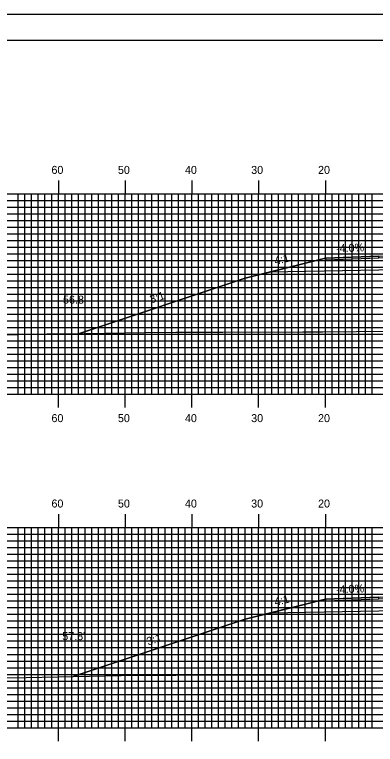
# Model space of a CAD drawing. Extents: x 1787763 to 1788106, y 442591 to 442811.
# Drawn here: x 1787862.1 to 1787916.1, y 442701.2 to 442810.5 of the extents above; entities that cross this region are included whole.
import ezdxf

# ---------------------------------------------------------------- set-up
doc = ezdxf.new("R2010")
doc.units = 0
for name, color, linetype in [('ANNOTATION', 7, 'Continuous'), ('BORDER', 7, 'Continuous'), ('D_Roadway_Centerline', 7, 'Continuous'), ('D_Roadway_Edge_Shoulder', 7, 'Continuous'), ('D_Roadway_SlopeLines', 7, 'Continuous'), ('D_Roadway_SubGrade', 7, 'Continuous'), ('D_Text_Standard', 7, 'Continuous'), ('H_V ANNOTATION', 7, 'Continuous'), ('MAJOR', 7, 'Continuous'), ('MINOR', 7, 'Continuous'), ('PLOT BOUNDARY', 7, 'Continuous'), ('S_Roadway_Centerline', 7, 'Continuous')]:
    doc.layers.add(name, color=color, linetype=linetype)

msp = doc.modelspace()

# ---------------------------------------------------------------- linework, layer by layer
at = {"layer": 'BORDER'}
msp.add_lwpolyline([(1787779.02, 442596.67), (1788099.02, 442596.67), (1788099.02, 442806.67), (1787779.02, 442806.67)], close=True, dxfattribs=at)
at = {"layer": 'D_Roadway_Centerline'}
for points in [[(1787871.78, 442762.76), (1787896.62, 442771.03), (1787900.25, 442771.94), (1787908.62, 442774.03), (1787916.62, 442774.35), (1787928.62, 442774.62), (1787940.62, 442774.88), (1787948.62, 442774.56), (1787956.98, 442772.47), (1787960.62, 442771.56), (1787984.39, 442763.64)], [(1787870.86, 442711.34), (1787896.62, 442719.93), (1787900.25, 442720.84), (1787908.62, 442722.93), (1787916.62, 442723.25), (1787928.62, 442723.51), (1787940.62, 442723.78), (1787948.62, 442723.46), (1787956.98, 442721.37), (1787960.62, 442720.46), (1787987.68, 442711.43)]]:
    msp.add_lwpolyline(points, dxfattribs=at)
at = {"layer": 'D_Roadway_Edge_Shoulder'}
for points in [[(1787916.62, 442774.35), (1787908.62, 442774.03), (1787908.62, 442773.78), (1787916.62, 442774.1)], [(1787916.62, 442723.25), (1787908.62, 442722.93), (1787908.62, 442722.68), (1787916.62, 442723)]]:
    msp.add_lwpolyline(points, close=True, dxfattribs=at)
at = {"layer": 'D_Roadway_SlopeLines'}
for points in [[(1787908.62, 442774.03), (1787896.62, 442771.03), (1787871.78, 442762.76)], [(1787908.62, 442722.93), (1787896.62, 442719.93), (1787870.86, 442711.34)]]:
    msp.add_lwpolyline(points, dxfattribs=at)
at = {"layer": 'D_Roadway_SubGrade'}
for points in [[(1787916.62, 442772.27), (1787900.25, 442771.94), (1787908.62, 442774.03), (1787908.62, 442773.78), (1787916.62, 442774.1), (1787928.62, 442774.37), (1787940.62, 442774.63), (1787948.62, 442774.31), (1787948.62, 442774.56), (1787956.98, 442772.47), (1787940.62, 442772.8), (1787928.62, 442772.54)], [(1787916.62, 442721.16), (1787900.25, 442720.84), (1787908.62, 442722.93), (1787908.62, 442722.68), (1787916.62, 442723), (1787928.62, 442723.26), (1787940.62, 442723.53), (1787948.62, 442723.21), (1787948.62, 442723.46), (1787956.98, 442721.37), (1787940.62, 442721.69), (1787928.62, 442721.43)]]:
    msp.add_lwpolyline(points, close=True, dxfattribs=at)
at = {"layer": 'MAJOR'}
for p, q in [((1787868.62, 442785.67), (1787868.62, 442783.67)), ((1787878.62, 442785.67), (1787878.62, 442783.67)), ((1787888.62, 442785.67), (1787888.62, 442783.67)), ((1787898.62, 442785.67), (1787898.62, 442783.67)), ((1787908.62, 442785.67), (1787908.62, 442783.67)), ((1787788.62, 442783.67), (1788068.62, 442783.67)), ((1787788.62, 442783.67), (1788068.62, 442783.67)), ((1787868.62, 442753.67), (1787868.62, 442783.67)), ((1787878.62, 442753.67), (1787878.62, 442783.67)), ((1787888.62, 442753.67), (1787888.62, 442783.67)), ((1787898.62, 442753.67), (1787898.62, 442783.67)), ((1787908.62, 442753.67), (1787908.62, 442783.67)), ((1787788.62, 442778.67), (1788068.62, 442778.67)), ((1787788.62, 442773.67), (1788068.62, 442773.67)), ((1787788.62, 442768.67), (1788068.62, 442768.67)), ((1787788.62, 442763.67), (1788068.62, 442763.67)), ((1787788.62, 442758.67), (1788068.62, 442758.67)), ((1787788.62, 442753.67), (1788068.62, 442753.67)), ((1787788.62, 442753.67), (1788068.62, 442753.67)), ((1787868.62, 442751.66), (1787868.62, 442753.67)), ((1787878.62, 442751.66), (1787878.62, 442753.67)), ((1787888.62, 442751.66), (1787888.62, 442753.67)), ((1787898.62, 442751.66), (1787898.62, 442753.67)), ((1787908.62, 442751.66), (1787908.62, 442753.67)), ((1787868.62, 442735.67), (1787868.62, 442733.67)), ((1787878.62, 442735.67), (1787878.62, 442733.67)), ((1787888.62, 442735.67), (1787888.62, 442733.67)), ((1787898.62, 442735.67), (1787898.62, 442733.67)), ((1787908.62, 442735.67), (1787908.62, 442733.67)), ((1787788.62, 442733.67), (1788068.62, 442733.67)), ((1787788.62, 442733.67), (1788068.62, 442733.67)), ((1787868.62, 442703.67), (1787868.62, 442733.67)), ((1787878.62, 442703.67), (1787878.62, 442733.67)), ((1787888.62, 442703.67), (1787888.62, 442733.67)), ((1787898.62, 442703.67), (1787898.62, 442733.67)), ((1787908.62, 442703.67), (1787908.62, 442733.67)), ((1787788.62, 442728.67), (1788068.62, 442728.67)), ((1787788.62, 442723.67), (1788068.62, 442723.67)), ((1787788.62, 442718.67), (1788068.62, 442718.67)), ((1787788.62, 442713.67), (1788068.62, 442713.67)), ((1787788.62, 442708.67), (1788068.62, 442708.67)), ((1787788.62, 442703.67), (1788068.62, 442703.67)), ((1787788.62, 442703.67), (1788068.62, 442703.67)), ((1787868.62, 442701.66), (1787868.62, 442703.67)), ((1787878.62, 442701.66), (1787878.62, 442703.67)), ((1787888.62, 442701.66), (1787888.62, 442703.67)), ((1787898.62, 442701.66), (1787898.62, 442703.67)), ((1787908.62, 442701.66), (1787908.62, 442703.67))]:
    msp.add_line(p, q, dxfattribs=at)
at = {"layer": 'MINOR'}
for p, q in [((1787862.62, 442753.67), (1787862.62, 442783.67)), ((1787863.62, 442753.67), (1787863.62, 442783.67)), ((1787864.62, 442753.67), (1787864.62, 442783.67)), ((1787865.62, 442753.67), (1787865.62, 442783.67)), ((1787866.62, 442753.67), (1787866.62, 442783.67)), ((1787867.62, 442753.67), (1787867.62, 442783.67)), ((1787869.62, 442753.67), (1787869.62, 442783.67)), ((1787870.62, 442753.67), (1787870.62, 442783.67)), ((1787871.62, 442753.67), (1787871.62, 442783.67)), ((1787872.62, 442753.67), (1787872.62, 442783.67)), ((1787873.62, 442753.67), (1787873.62, 442783.67)), ((1787874.62, 442753.67), (1787874.62, 442783.67)), ((1787875.62, 442753.67), (1787875.62, 442783.67)), ((1787876.62, 442753.67), (1787876.62, 442783.67)), ((1787877.62, 442753.67), (1787877.62, 442783.67)), ((1787879.62, 442753.67), (1787879.62, 442783.67)), ((1787880.62, 442753.67), (1787880.62, 442783.67)), ((1787881.62, 442753.67), (1787881.62, 442783.67)), ((1787882.62, 442753.67), (1787882.62, 442783.67)), ((1787883.62, 442753.67), (1787883.62, 442783.67)), ((1787884.62, 442753.67), (1787884.62, 442783.67)), ((1787885.62, 442753.67), (1787885.62, 442783.67)), ((1787886.62, 442753.67), (1787886.62, 442783.67)), ((1787887.62, 442753.67), (1787887.62, 442783.67)), ((1787889.62, 442753.67), (1787889.62, 442783.67)), ((1787890.62, 442753.67), (1787890.62, 442783.67)), ((1787891.62, 442753.67), (1787891.62, 442783.67)), ((1787892.62, 442753.67), (1787892.62, 442783.67)), ((1787893.62, 442753.67), (1787893.62, 442783.67)), ((1787894.62, 442753.67), (1787894.62, 442783.67)), ((1787895.62, 442753.67), (1787895.62, 442783.67)), ((1787896.62, 442753.67), (1787896.62, 442783.67)), ((1787897.62, 442753.67), (1787897.62, 442783.67)), ((1787899.62, 442753.67), (1787899.62, 442783.67)), ((1787900.62, 442753.67), (1787900.62, 442783.67)), ((1787901.62, 442753.67), (1787901.62, 442783.67)), ((1787902.62, 442753.67), (1787902.62, 442783.67)), ((1787903.62, 442753.67), (1787903.62, 442783.67)), ((1787904.62, 442753.67), (1787904.62, 442783.67)), ((1787905.62, 442753.67), (1787905.62, 442783.67)), ((1787906.62, 442753.67), (1787906.62, 442783.67)), ((1787907.62, 442753.67), (1787907.62, 442783.67)), ((1787909.62, 442753.67), (1787909.62, 442783.67)), ((1787910.62, 442753.67), (1787910.62, 442783.67)), ((1787911.62, 442753.67), (1787911.62, 442783.67)), ((1787912.62, 442753.67), (1787912.62, 442783.67)), ((1787913.62, 442753.67), (1787913.62, 442783.67)), ((1787914.62, 442753.67), (1787914.62, 442783.67)), ((1787915.62, 442753.67), (1787915.62, 442783.67)), ((1787788.62, 442782.67), (1788068.62, 442782.67)), ((1787788.62, 442781.67), (1788068.62, 442781.67)), ((1787788.62, 442780.67), (1788068.62, 442780.67)), ((1787788.62, 442779.67), (1788068.62, 442779.67)), ((1787788.62, 442777.67), (1788068.62, 442777.67)), ((1787788.62, 442776.67), (1788068.62, 442776.67)), ((1787788.62, 442775.67), (1788068.62, 442775.67)), ((1787788.62, 442774.67), (1788068.62, 442774.67)), ((1787788.62, 442772.67), (1788068.62, 442772.67)), ((1787788.62, 442771.67), (1788068.62, 442771.67)), ((1787788.62, 442770.67), (1788068.62, 442770.67)), ((1787788.62, 442769.67), (1788068.62, 442769.67)), ((1787788.62, 442767.67), (1788068.62, 442767.67)), ((1787788.62, 442766.67), (1788068.62, 442766.67)), ((1787788.62, 442765.67), (1788068.62, 442765.67)), ((1787788.62, 442764.67), (1788068.62, 442764.67)), ((1787788.62, 442762.67), (1788068.62, 442762.67)), ((1787788.62, 442761.67), (1788068.62, 442761.67)), ((1787788.62, 442760.67), (1788068.62, 442760.67)), ((1787788.62, 442759.67), (1788068.62, 442759.67)), ((1787788.62, 442757.67), (1788068.62, 442757.67)), ((1787788.62, 442756.67), (1788068.62, 442756.67)), ((1787788.62, 442755.67), (1788068.62, 442755.67)), ((1787788.62, 442754.67), (1788068.62, 442754.67)), ((1787862.62, 442703.67), (1787862.62, 442733.67)), ((1787863.62, 442703.67), (1787863.62, 442733.67)), ((1787864.62, 442703.67), (1787864.62, 442733.67)), ((1787865.62, 442703.67), (1787865.62, 442733.67)), ((1787866.62, 442703.67), (1787866.62, 442733.67)), ((1787867.62, 442703.67), (1787867.62, 442733.67)), ((1787869.62, 442703.67), (1787869.62, 442733.67)), ((1787870.62, 442703.67), (1787870.62, 442733.67)), ((1787871.62, 442703.67), (1787871.62, 442733.67)), ((1787872.62, 442703.67), (1787872.62, 442733.67)), ((1787873.62, 442703.67), (1787873.62, 442733.67)), ((1787874.62, 442703.67), (1787874.62, 442733.67)), ((1787875.62, 442703.67), (1787875.62, 442733.67)), ((1787876.62, 442703.67), (1787876.62, 442733.67)), ((1787877.62, 442703.67), (1787877.62, 442733.67)), ((1787879.62, 442703.67), (1787879.62, 442733.67)), ((1787880.62, 442703.67), (1787880.62, 442733.67)), ((1787881.62, 442703.67), (1787881.62, 442733.67)), ((1787882.62, 442703.67), (1787882.62, 442733.67)), ((1787883.62, 442703.67), (1787883.62, 442733.67)), ((1787884.62, 442703.67), (1787884.62, 442733.67)), ((1787885.62, 442703.67), (1787885.62, 442733.67)), ((1787886.62, 442703.67), (1787886.62, 442733.67)), ((1787887.62, 442703.67), (1787887.62, 442733.67)), ((1787889.62, 442703.67), (1787889.62, 442733.67)), ((1787890.62, 442703.67), (1787890.62, 442733.67)), ((1787891.62, 442703.67), (1787891.62, 442733.67)), ((1787892.62, 442703.67), (1787892.62, 442733.67)), ((1787893.62, 442703.67), (1787893.62, 442733.67)), ((1787894.62, 442703.67), (1787894.62, 442733.67)), ((1787895.62, 442703.67), (1787895.62, 442733.67)), ((1787896.62, 442703.67), (1787896.62, 442733.67)), ((1787897.62, 442703.67), (1787897.62, 442733.67)), ((1787899.62, 442703.67), (1787899.62, 442733.67)), ((1787900.62, 442703.67), (1787900.62, 442733.67)), ((1787901.62, 442703.67), (1787901.62, 442733.67)), ((1787902.62, 442703.67), (1787902.62, 442733.67)), ((1787903.62, 442703.67), (1787903.62, 442733.67)), ((1787904.62, 442703.67), (1787904.62, 442733.67)), ((1787905.62, 442703.67), (1787905.62, 442733.67)), ((1787906.62, 442703.67), (1787906.62, 442733.67)), ((1787907.62, 442703.67), (1787907.62, 442733.67)), ((1787909.62, 442703.67), (1787909.62, 442733.67)), ((1787910.62, 442703.67), (1787910.62, 442733.67)), ((1787911.62, 442703.67), (1787911.62, 442733.67)), ((1787912.62, 442703.67), (1787912.62, 442733.67)), ((1787913.62, 442703.67), (1787913.62, 442733.67)), ((1787914.62, 442703.67), (1787914.62, 442733.67)), ((1787915.62, 442703.67), (1787915.62, 442733.67)), ((1787788.62, 442732.67), (1788068.62, 442732.67)), ((1787788.62, 442731.67), (1788068.62, 442731.67)), ((1787788.62, 442730.67), (1788068.62, 442730.67)), ((1787788.62, 442729.67), (1788068.62, 442729.67)), ((1787788.62, 442727.67), (1788068.62, 442727.67)), ((1787788.62, 442726.67), (1788068.62, 442726.67)), ((1787788.62, 442725.67), (1788068.62, 442725.67)), ((1787788.62, 442724.67), (1788068.62, 442724.67)), ((1787788.62, 442722.67), (1788068.62, 442722.67)), ((1787788.62, 442721.67), (1788068.62, 442721.67)), ((1787788.62, 442720.67), (1788068.62, 442720.67)), ((1787788.62, 442719.67), (1788068.62, 442719.67)), ((1787788.62, 442717.67), (1788068.62, 442717.67)), ((1787788.62, 442716.67), (1788068.62, 442716.67)), ((1787788.62, 442715.67), (1788068.62, 442715.67)), ((1787788.62, 442714.67), (1788068.62, 442714.67)), ((1787788.62, 442712.67), (1788068.62, 442712.67)), ((1787788.62, 442711.67), (1788068.62, 442711.67)), ((1787788.62, 442710.67), (1788068.62, 442710.67)), ((1787788.62, 442709.67), (1788068.62, 442709.67)), ((1787788.62, 442707.67), (1788068.62, 442707.67)), ((1787788.62, 442706.67), (1788068.62, 442706.67)), ((1787788.62, 442705.67), (1788068.62, 442705.67)), ((1787788.62, 442704.67), (1788068.62, 442704.67))]:
    msp.add_line(p, q, dxfattribs=at)
at = {"layer": 'PLOT BOUNDARY'}
msp.add_lwpolyline([(1787762.83, 442590.55), (1788102.83, 442590.55), (1788102.83, 442810.55), (1787762.83, 442810.55)], close=True, dxfattribs=at)
at = {"layer": 'S_Roadway_Centerline'}
for points in [[(1787860.53, 442762.53), (1787866.88, 442762.69), (1787872.49, 442762.77), (1787881.63, 442762.9), (1787886.22, 442762.95), (1787893.24, 442762.94), (1787905.25, 442763), (1787908.26, 442762.98), (1787913.29, 442763.06), (1787924.29, 442763.15), (1787932.21, 442763.26), (1787943.5, 442763.2), (1787945.27, 442763.18), (1787955.82, 442763.16), (1787962.52, 442763.13), (1787967.92, 442763.25), (1787976.54, 442763.53), (1787981.61, 442763.64), (1787991.77, 442763.65)], [(1787860.39, 442711.13), (1787863.81, 442711.2), (1787878.04, 442711.49), (1787894.44, 442711.58), (1787896.98, 442711.59), (1787908.11, 442711.56), (1787916.2, 442711.63), (1787925.96, 442711.73), (1787931.85, 442711.76), (1787935.76, 442711.79), (1787943.88, 442711.79), (1787955.19, 442711.7), (1787957.42, 442711.68), (1787967.75, 442711.6), (1787974.69, 442711.45), (1787980.13, 442711.43), (1787988.93, 442711.44), (1787993.21, 442711.48)]]:
    msp.add_lwpolyline(points, dxfattribs=at)

# ---------------------------------------------------------------- texts
at = {"layer": 'ANNOTATION'}
for s, rotation, p in [('-4.0%', 2.2906, (1787910.25, 442774.9)), ('4:1', 14.0362, (1787901.15, 442773.03)), ('3:1', 18.4348, (1787882.54, 442767.25)), ('-4.0%', 2.2906, (1787910.25, 442723.79)), ('4:1', 14.0362, (1787901.15, 442721.92)), ('3:1', 18.4348, (1787882.08, 442715.99))]:
    msp.add_text(s, height=1.2, rotation=rotation, dxfattribs=at).set_placement(p)
at = {"layer": 'D_Text_Standard'}
for s, p in [("56.8'", (1787869.33, 442767.23)), ("57.8'", (1787869.21, 442716.8))]:
    msp.add_text(s, height=1.2, dxfattribs=at).set_placement(p)
at = {"layer": 'H_V ANNOTATION'}
for s, p in [('60', (1787867.59, 442786.67)), ('50', (1787877.55, 442786.67)), ('40', (1787887.59, 442786.67)), ('30', (1787897.51, 442786.67)), ('20', (1787907.53, 442786.67)), ('60', (1787867.59, 442749.47)), ('50', (1787877.55, 442749.47)), ('40', (1787887.59, 442749.47)), ('30', (1787897.51, 442749.47)), ('20', (1787907.53, 442749.47)), ('60', (1787867.59, 442736.67)), ('50', (1787877.55, 442736.67)), ('40', (1787887.59, 442736.67)), ('30', (1787897.51, 442736.67)), ('20', (1787907.53, 442736.67))]:
    msp.add_text(s, height=1.2, dxfattribs=at).set_placement(p)

doc.saveas('drawing.dxf')
